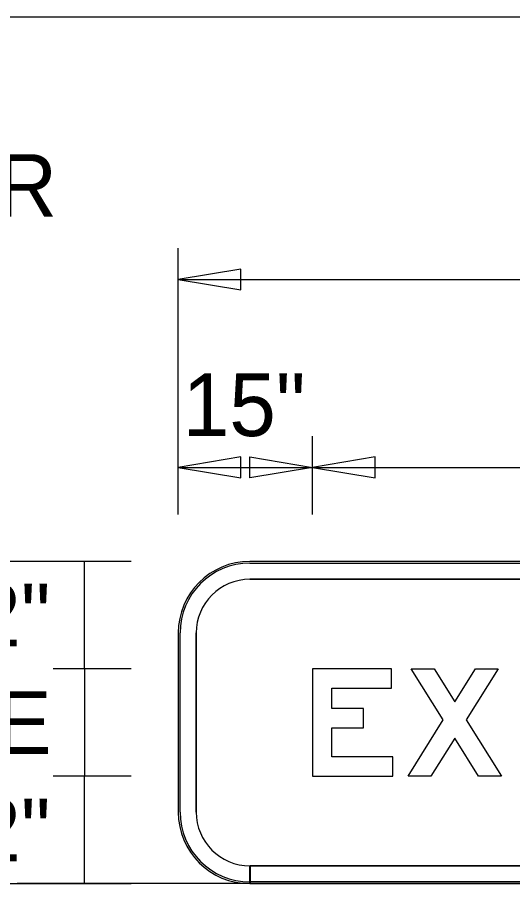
# Model space of a CAD drawing. Extents: x 2149934 to 2150188, y 145113 to 145238.
# Drawn here: x 2150091.28 to 2150095.89, y 145158.88 to 145166.95 of the extents above; entities that cross this region are included whole.
import ezdxf

# ---------------------------------------------------------------- set-up
doc = ezdxf.new("R2010")
doc.units = 0
for name, color, linetype in [('GSBWFILL', 7, 'Continuous'), ('GSCOLORFILL', 7, 'Continuous'), ('GSDIMS', 7, 'Continuous'), ('GSOUTLINE', 7, 'Continuous'), ('Level 1', 7, 'Continuous')]:
    doc.layers.add(name, color=color, linetype=linetype)

msp = doc.modelspace()

# ---------------------------------------------------------------- linework, layer by layer
at = {"layer": 'GSBWFILL'}
for p, q in [((2150105.112, 145161.8839), (2150093.4449, 145161.8839)), ((2150093.4449, 145161.7172), (2150105.112, 145161.7172)), ((2150092.7782, 145161.2172), (2150092.7782, 145159.5496)), ((2150092.9449, 145159.5496), (2150092.9449, 145161.2172)), ((2150093.4449, 145158.8829), (2150093.4449, 145159.0496)), ((2150105.112, 145159.0496), (2150093.4465, 145159.0496)), ((2150093.4465, 145159.0496), (2150093.4465, 145158.8829)), ((2150104.7786, 145158.8829), (2150091.2786, 145158.8829)), ((2150093.4465, 145158.8829), (2150105.112, 145158.8829))]:
    msp.add_line(p, q, dxfattribs=at)
for points in [[(2150094.7783, 145160.0634), (2150094.2083, 145160.0634), (2150094.2083, 145160.3324), (2150094.5033, 145160.3324), (2150094.5033, 145160.5124), (2150094.2083, 145160.5124), (2150094.2083, 145160.7034), (2150094.7633, 145160.7034), (2150094.7633, 145160.8834), (2150094.0283, 145160.8834), (2150094.0283, 145159.8834), (2150094.7783, 145159.8834)], [(2150095.5758, 145159.8834), (2150095.3533, 145160.238), (2150095.1308, 145159.8834), (2150094.9183, 145159.8834), (2150095.2471, 145160.4073), (2150094.9483, 145160.8834), (2150095.1608, 145160.8834), (2150095.3533, 145160.5766), (2150095.5458, 145160.8834), (2150095.7583, 145160.8834), (2150095.4596, 145160.4073), (2150095.7883, 145159.8834)]]:
    msp.add_lwpolyline(points, close=True, dxfattribs=at)
for centre, radius, start, end in [((2150093.4449, 145161.2172), 0.6667, 90, 180), ((2150093.4449, 145161.2172), 0.5, 90, 180), ((2150093.4449, 145159.5496), 0.6667, 180, 270), ((2150093.4449, 145159.5496), 0.5, 180, 270)]:
    msp.add_arc(centre, radius, start, end, dxfattribs=at)
at = {"layer": 'GSCOLORFILL'}
for p, q in [((2150105.112, 145161.8839), (2150093.4449, 145161.8839)), ((2150105.112, 145161.8839), (2150093.4449, 145161.8839)), ((2150105.112, 145161.8839), (2150093.4449, 145161.8839)), ((2150093.4449, 145161.8672), (2150105.112, 145161.8672)), ((2150093.4449, 145161.7172), (2150105.112, 145161.7172)), ((2150092.7782, 145161.2172), (2150092.7782, 145159.5496)), ((2150092.7782, 145161.2172), (2150092.7782, 145159.5496)), ((2150092.7782, 145161.2172), (2150092.7782, 145159.5496)), ((2150092.7949, 145159.5496), (2150092.7949, 145161.2172)), ((2150092.9449, 145159.5496), (2150092.9449, 145161.2172)), ((2150093.4449, 145158.8829), (2150093.4449, 145159.0496)), ((2150105.112, 145159.0496), (2150093.4465, 145159.0496)), ((2150093.4465, 145159.0496), (2150093.4465, 145158.8829)), ((2150104.7786, 145158.8829), (2150091.2786, 145158.8829)), ((2150104.7786, 145158.8829), (2150091.2786, 145158.8829)), ((2150104.7786, 145158.8829), (2150091.2786, 145158.8829)), ((2150093.4449, 145158.8829), (2150093.4449, 145158.8996)), ((2150093.4449, 145158.8829), (2150105.112, 145158.8829)), ((2150105.112, 145158.8996), (2150093.445, 145158.8996)), ((2150093.445, 145158.8996), (2150093.445, 145158.8829)), ((2150093.445, 145158.8829), (2150105.112, 145158.8829)), ((2150093.4465, 145158.8829), (2150105.112, 145158.8829))]:
    msp.add_line(p, q, dxfattribs=at)
for points in [[(2150094.7783, 145160.0634), (2150094.2083, 145160.0634), (2150094.2083, 145160.3324), (2150094.5033, 145160.3324), (2150094.5033, 145160.5124), (2150094.2083, 145160.5124), (2150094.2083, 145160.7034), (2150094.7633, 145160.7034), (2150094.7633, 145160.8834), (2150094.0283, 145160.8834), (2150094.0283, 145159.8834), (2150094.7783, 145159.8834)], [(2150095.5758, 145159.8834), (2150095.3533, 145160.238), (2150095.1308, 145159.8834), (2150094.9183, 145159.8834), (2150095.2471, 145160.4073), (2150094.9483, 145160.8834), (2150095.1608, 145160.8834), (2150095.3533, 145160.5766), (2150095.5458, 145160.8834), (2150095.7583, 145160.8834), (2150095.4596, 145160.4073), (2150095.7883, 145159.8834)]]:
    msp.add_lwpolyline(points, close=True, dxfattribs=at)
for centre, radius, start, end in [((2150093.4449, 145161.2172), 0.6667, 90, 180), ((2150093.4449, 145161.2172), 0.6667, 90, 180), ((2150093.4449, 145161.2172), 0.6667, 90, 180), ((2150093.4449, 145161.2172), 0.65, 90, 180), ((2150093.4449, 145161.2172), 0.5, 90, 180), ((2150093.4449, 145159.5496), 0.6667, 180, 270), ((2150093.4449, 145159.5496), 0.6667, 180, 270), ((2150093.4449, 145159.5496), 0.6667, 180, 270), ((2150093.4449, 145159.5496), 0.65, 180, 270), ((2150093.4449, 145159.5496), 0.5, 180, 270)]:
    msp.add_arc(centre, radius, start, end, dxfattribs=at)
at = {"layer": 'GSDIMS'}
for p, q in [((2150092.7782, 145164.0714), (2150092.7782, 145164.8006)), ((2150092.7782, 145164.5089), (2150105.7788, 145164.5089)), ((2150092.7782, 145162.3214), (2150092.7782, 145164.0714)), ((2150092.7782, 145162.3214), (2150092.7782, 145163.0506)), ((2150094.0283, 145162.3214), (2150094.0283, 145163.0506)), ((2150094.0283, 145162.3214), (2150094.0283, 145163.0506)), ((2150092.7782, 145162.7589), (2150094.0283, 145162.7589)), ((2150094.0283, 145162.7589), (2150104.8445, 145162.7589)), ((2150092.3407, 145161.8839), (2150088.8407, 145161.8839)), ((2150092.3407, 145161.8839), (2150091.6115, 145161.8839)), ((2150091.9032, 145160.8834), (2150091.9032, 145161.8839)), ((2150092.3407, 145160.8834), (2150091.6115, 145160.8834)), ((2150092.3407, 145160.8834), (2150091.6115, 145160.8834)), ((2150091.9032, 145160.8834), (2150091.9032, 145159.8834)), ((2150092.3407, 145159.8834), (2150091.6115, 145159.8834)), ((2150092.3407, 145159.8834), (2150091.6115, 145159.8834)), ((2150091.9032, 145158.8828), (2150091.9032, 145159.8834)), ((2150092.3407, 145158.8828), (2150088.8407, 145158.8828)), ((2150092.3407, 145158.8828), (2150091.6115, 145158.8828))]:
    msp.add_line(p, q, dxfattribs=at)
for points in [[(2150092.7782, 145164.5089), (2150093.3615, 145164.4117), (2150093.3615, 145164.6061)], [(2150092.7782, 145162.7589), (2150093.3615, 145162.6617), (2150093.3615, 145162.8561)], [(2150094.0283, 145162.7589), (2150093.445, 145162.6617), (2150093.445, 145162.8561)], [(2150094.0283, 145162.7589), (2150094.6117, 145162.6617), (2150094.6117, 145162.8561)]]:
    msp.add_lwpolyline(points, close=True, dxfattribs=at)
at = {"layer": 'GSOUTLINE'}
for p, q in [((2150105.112, 145161.8839), (2150093.4449, 145161.8839)), ((2150105.112, 145161.7172), (2150093.4449, 145161.7172)), ((2150092.7782, 145161.2172), (2150092.7782, 145159.5496)), ((2150092.9449, 145161.2172), (2150092.9449, 145159.5496)), ((2150093.4449, 145159.0496), (2150105.112, 145159.0496)), ((2150104.7786, 145158.8829), (2150091.2786, 145158.8829)), ((2150093.4449, 145158.8829), (2150105.112, 145158.8829))]:
    msp.add_line(p, q, dxfattribs=at)
for points in [[(2150094.7783, 145160.0634), (2150094.2083, 145160.0634), (2150094.2083, 145160.3324), (2150094.5033, 145160.3324), (2150094.5033, 145160.5124), (2150094.2083, 145160.5124), (2150094.2083, 145160.7034), (2150094.7633, 145160.7034), (2150094.7633, 145160.8834), (2150094.0283, 145160.8834), (2150094.0283, 145159.8834), (2150094.7783, 145159.8834)], [(2150095.5758, 145159.8834), (2150095.3533, 145160.238), (2150095.1308, 145159.8834), (2150094.9183, 145159.8834), (2150095.2471, 145160.4073), (2150094.9483, 145160.8834), (2150095.1608, 145160.8834), (2150095.3533, 145160.5766), (2150095.5458, 145160.8834), (2150095.7583, 145160.8834), (2150095.4596, 145160.4073), (2150095.7883, 145159.8834)]]:
    msp.add_lwpolyline(points, close=True, dxfattribs=at)
for centre, radius, start, end in [((2150093.4449, 145161.2172), 0.6667, 90, 180), ((2150093.4449, 145161.2172), 0.5, 90, 180), ((2150093.4449, 145159.5496), 0.6667, 180, 270), ((2150093.4449, 145159.5496), 0.5, 180, 270)]:
    msp.add_arc(centre, radius, start, end, dxfattribs=at)
at = {"layer": 'Level 1'}
msp.add_line((2150135.4472, 145166.9499), (2150017.5574, 145166.9499), dxfattribs=at)

# ---------------------------------------------------------------- texts
at = {"layer": 'GSDIMS'}
for s, p in [('BORDER', (2150088.3121, 145165.0923)), ('15"', (2150092.8194, 145163.0506)), ('12"', (2150090.4438, 145161.0919)), ('12"E', (2150089.9332, 145160.0917)), ('12"', (2150090.4438, 145159.0914))]:
    msp.add_text(s, height=0.58333, dxfattribs=at).set_placement(p)

doc.saveas('drawing.dxf')
